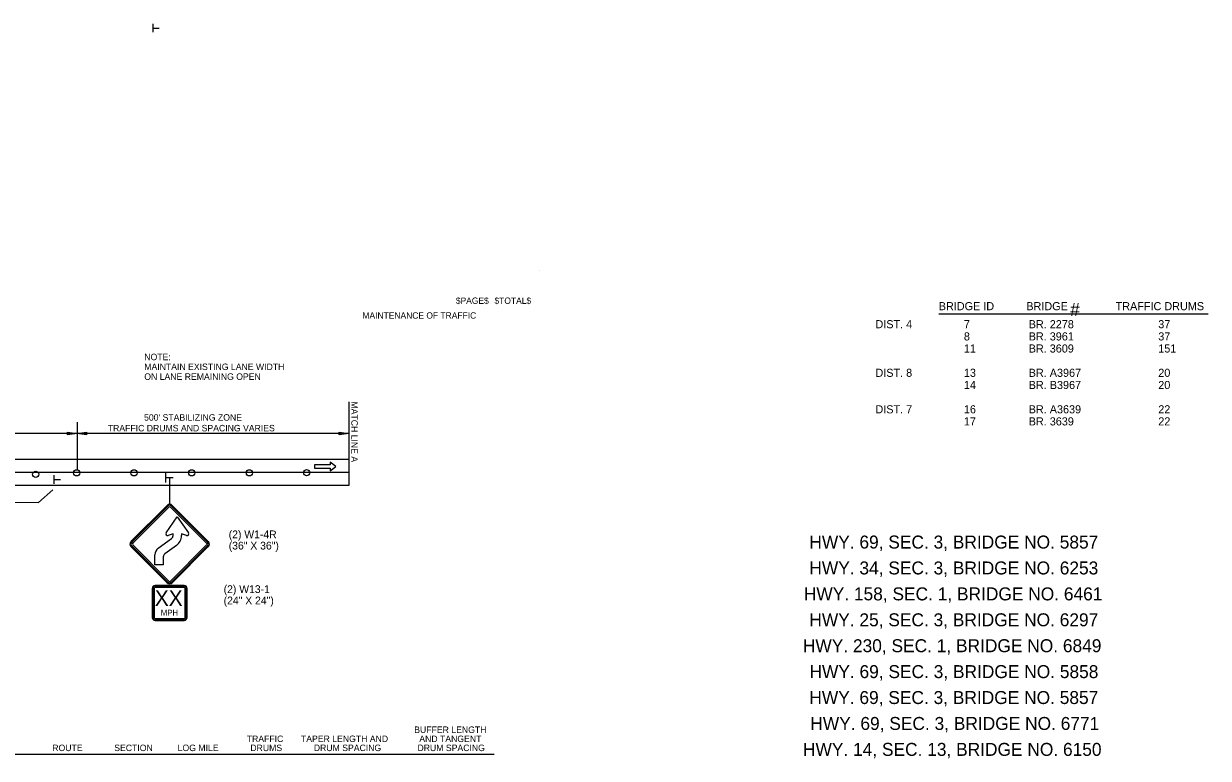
# Model space of a CAD drawing. Extents: x 1930579 to 1937521, y 596183 to 597566.
# Drawn here: x 1936202 to 1937299, y 596886 to 597566 of the extents above; entities that cross this region are included whole.
import ezdxf

# ---------------------------------------------------------------- set-up
doc = ezdxf.new("R2010")
doc.units = 0
for name, color, linetype in [('Default', 7, 'Continuous'), ('P_TC_Signs_Permanent', 7, 'Continuous'), ('R_Annotation', 7, 'Continuous'), ('R_Border', 7, 'Continuous'), ('R_Striping', 7, 'Continuous')]:
    doc.layers.add(name, color=color, linetype=linetype)

msp = doc.modelspace()

# ---------------------------------------------------------------- linework, layer by layer
at = {"layer": 'Default'}
for p, q in [((1936321.9, 597558.1), (1936321.9, 597566)), ((1936322, 597562), (1936327.4, 597562)), ((1936503, 597215.8), (1936503, 597138.5)), ((1936251.3, 597197), (1936251.3, 597152.4)), ((1936251.3, 597186.5), (1935884.1, 597186.5)), ((1936242.4, 597185.2), (1936242.4, 597187.8)), ((1936242.4, 597187.8), (1936251.3, 597186.5)), ((1936251.3, 597186.5), (1936242.4, 597185.2)), ((1936251.3, 597186.5), (1936260.2, 597187.8)), ((1936503, 597186.5), (1936251.3, 597186.5)), ((1936260.2, 597185.2), (1936251.3, 597186.5)), ((1936260.2, 597187.8), (1936260.2, 597185.2)), ((1936494.2, 597185.2), (1936494.2, 597187.8)), ((1936494.2, 597187.8), (1936503, 597186.5)), ((1936503, 597186.5), (1936494.2, 597185.2)), ((1936503, 597162.5), (1935188.5, 597162.5)), ((1936503, 597150.5), (1935188.5, 597150.5)), ((1936230.3, 597139.9), (1936230.3, 597147.9)), ((1936230.4, 597143.8), (1936235.9, 597143.8)), ((1936333.7, 597141), (1936333.7, 597150.6)), ((1936333.9, 597145.8), (1936340.4, 597145.8)), ((1936503, 597138.5), (1935188.5, 597138.5))]:
    msp.add_line(p, q, dxfattribs=at)
for centre in [(1936213.1, 597148.8), (1936251, 597150.1), (1936304.1, 597150.1), (1936357.6, 597150.1), (1936411, 597150.1), (1936463.9, 597150.3)]:
    msp.add_circle(centre, 2.87, dxfattribs=at)
at = {"layer": 'P_TC_Signs_Permanent'}
for p, q in [((1936301.3, 597086.5), (1936334.8, 597119.9)), ((1936302, 597085.9), (1936335.4, 597119.3)), ((1936336.3, 597118.4), (1936302.9, 597084.9)), ((1936371.3, 597084.9), (1936337.9, 597118.4)), ((1936338.9, 597119.3), (1936372.3, 597085.9)), ((1936339.5, 597119.9), (1936372.9, 597086.5)), ((1936326.6, 597080.4), (1936338.9, 597089.3)), ((1936334.8, 597048.3), (1936301.3, 597081.8)), ((1936335.4, 597049), (1936302, 597082.4)), ((1936302.9, 597083.3), (1936336.3, 597049.9)), ((1936343.5, 597082.9), (1936332.6, 597075.1)), ((1936337.9, 597049.9), (1936371.3, 597083.3)), ((1936372.3, 597082.4), (1936338.9, 597049)), ((1936372.9, 597081.8), (1936339.5, 597048.3)), ((1936320.9, 597043.1), (1936320.9, 597016.1)), ((1936321.6, 597043.1), (1936321.6, 597016.1)), ((1936322.7, 597043.1), (1936322.7, 597016.1)), ((1936350.6, 597045.8), (1936323.6, 597045.8)), ((1936350.6, 597045.1), (1936323.6, 597045.1)), ((1936350.6, 597044), (1936323.6, 597044)), ((1936351.5, 597016.1), (1936351.5, 597043.1)), ((1936352.7, 597016.1), (1936352.7, 597043.1)), ((1936353.3, 597016.1), (1936353.3, 597043.1)), ((1936323.6, 597015.2), (1936350.6, 597015.2)), ((1936323.6, 597014.1), (1936350.6, 597014.1)), ((1936323.6, 597013.4), (1936350.6, 597013.4))]:
    msp.add_line(p, q, dxfattribs=at)
for points in [[(1936333.9, 597094.4), (1936344.2, 597109.5), (1936354.5, 597094.4)], [(1936340.3, 597092), (1936340.3, 597093.5), (1936335.7, 597092)], [(1936352.7, 597092), (1936348.2, 597093.5), (1936348.2, 597092)], [(1936331.2, 597072.3), (1936331.2, 597065), (1936323.4, 597065), (1936323.4, 597074.1)]]:
    msp.add_lwpolyline(points, dxfattribs=at)
for centre, radius, start, end in [((1936337.1, 597117.6), 3.38, 45, 135), ((1936337.1, 597117.6), 2.47, 45, 135), ((1936337.1, 597117.6), 1.12, 45, 135), ((1936303.7, 597084.1), 3.37, 135, 225), ((1936303.7, 597084.1), 2.47, 135, 225), ((1936335.2, 597093.5), 1.57, 145.6763, 287.8128), ((1936336.9, 597092), 3.38, 305.7733, 0), ((1936336.9, 597092), 11.2, 305.7733, 0), ((1936353.2, 597093.5), 1.57, 252.1872, 34.3237), ((1936370.6, 597084.1), 2.47, 315, 45), ((1936370.6, 597084.1), 3.37, 315, 45), ((1936303.7, 597084.1), 1.12, 135, 225), ((1936331.2, 597074.1), 7.87, 125.7733, 180), ((1936334.6, 597072.3), 3.38, 125.7733, 180), ((1936370.6, 597084.1), 1.12, 315, 45), ((1936323.6, 597043.1), 2.7, 90, 180), ((1936323.6, 597043.1), 2.03, 90, 180), ((1936323.6, 597043.1), 0.9, 90, 180), ((1936337.1, 597050.7), 3.37, 225, 315), ((1936337.1, 597050.7), 2.47, 225, 315), ((1936337.1, 597050.7), 1.12, 225, 315), ((1936350.6, 597043.1), 2.7, 360, 90), ((1936350.6, 597043.1), 2.03, 360, 90), ((1936350.6, 597043.1), 0.9, 360, 90), ((1936323.6, 597016.1), 2.7, 180, 270), ((1936323.6, 597016.1), 2.03, 180, 270), ((1936323.6, 597016.1), 0.9, 180, 270), ((1936350.6, 597016.1), 2.7, 270, 360), ((1936350.6, 597016.1), 2.03, 270, 360), ((1936350.6, 597016.1), 0.9, 270, 360)]:
    msp.add_arc(centre, radius, start, end, dxfattribs=at)
at = {"layer": 'R_Annotation'}
for p, q in [((1937049.3, 597297.3), (1937298.9, 597297.3)), ((1936337.1, 597145.8), (1936337.1, 597120.9)), ((1936090.3, 596889.7), (1936637.5, 596889.7))]:
    msp.add_line(p, q, dxfattribs=at)
msp.add_lwpolyline([(1936008.1, 597131), (1936019.9, 597124), (1936099.1, 597124), (1936099.8, 597115.7), (1936102.6, 597123.3), (1936215.8, 597122.6), (1936229, 597134.4)], dxfattribs=at)
at = {"layer": 'R_Border'}
msp.add_line((1936679.4, 597337.3), (1936679.4, 597337.3), dxfattribs=at)
at = {"layer": 'R_Striping'}
msp.add_lwpolyline([(1936485.8, 597152), (1936491, 597156), (1936485.8, 597160), (1936485.8, 597157.5), (1936471.1, 597157.5), (1936471.1, 597154.5), (1936485.8, 597154.5)], close=True, dxfattribs=at)

# ---------------------------------------------------------------- texts
at = {"layer": 'Default'}
for s, height, rotation, p in [('MATCH LINE A', 6, 270, (1936505.3, 597216.2)), ("500' STABILIZING ZONE", 6, 360, (1936313.4, 597198.4)), ('TRAFFIC DRUMS AND SPACING VARIES', 6, 360, (1936279.8, 597188.5)), ('HWY. 69, SEC. 3, BRIDGE NO. 5857', 12, 360, (1936929.5, 597080)), ('HWY. 34, SEC. 3, BRIDGE NO. 6253', 12, 360, (1936929.5, 597056)), ('HWY. 158, SEC. 1, BRIDGE NO. 6461', 12, 360, (1936924.4, 597032)), ('HWY. 25, SEC. 3, BRIDGE NO. 6297', 12, 360, (1936929.5, 597008)), ('HWY. 230, SEC. 1, BRIDGE NO. 6849', 12, 360, (1936923.5, 596984)), ('HWY. 69, SEC. 3, BRIDGE NO. 5858', 12, 360, (1936929.6, 596960)), ('HWY. 69, SEC. 3, BRIDGE NO. 5857', 12, 360, (1936929.5, 596936)), ('HWY. 69, SEC. 3, BRIDGE NO. 6771', 12, 360, (1936930.4, 596912)), ('HWY. 14, SEC. 13, BRIDGE NO. 6150', 12, 360, (1936923.6, 596888))]:
    msp.add_text(s, height=height, rotation=rotation, dxfattribs=at).set_placement(p)
at = {"layer": 'P_TC_Signs_Permanent'}
for s, height, p in [('XX', 14.4, (1936323.4, 597026.9)), ('MPH', 5.4, (1936328.9, 597017.9))]:
    msp.add_text(s, height=height, rotation=360, dxfattribs=at).set_placement(p)
at = {"layer": 'R_Annotation'}
for s, height, p in [('BRIDGE ID', 7.5, (1937049.3, 597300.7)), ('BRIDGE ', 7.5, (1937130.4, 597300.7)), ('#', 12, (1937171, 597295.4)), ('TRAFFIC DRUMS', 7.5, (1937213.1, 597300.7)), ('DIST. 4', 7.5, (1936990.7, 597284)), ('7', 7.5, (1937072.6, 597284)), ('BR. 2278', 7.5, (1937132.6, 597284)), ('37', 7.5, (1937252.6, 597284)), ('8', 7.5, (1937072.6, 597272.7)), ('BR. 3961', 7.5, (1937132.6, 597272.7)), ('37', 7.5, (1937252.6, 597272.7)), ('11', 7.5, (1937072.6, 597261.5)), ('BR. 3609', 7.5, (1937132.6, 597261.5)), ('151', 7.5, (1937252.6, 597261.5)), ('NOTE:', 6, (1936313.6, 597254.4)), ('MAINTAIN EXISTING LANE WIDTH', 6, (1936313.6, 597245.3)), ('ON LANE REMAINING OPEN', 6, (1936313.6, 597236.2)), ('DIST. 8', 7.5, (1936990.7, 597239)), ('13', 7.5, (1937072.6, 597239)), ('BR. A3967', 7.5, (1937132.6, 597239)), ('20', 7.5, (1937252.6, 597239)), ('14', 7.5, (1937072.6, 597227.7)), ('BR. B3967', 7.5, (1937132.6, 597227.7)), ('20', 7.5, (1937252.6, 597227.7)), ('DIST. 7', 7.5, (1936990.7, 597205.2)), ('16', 7.5, (1937072.6, 597205.2)), ('BR. A3639', 7.5, (1937132.6, 597205.2)), ('22', 7.5, (1937252.6, 597205.2)), ('17', 7.5, (1937072.6, 597194)), ('BR. 3639', 7.5, (1937132.6, 597194)), ('22', 7.5, (1937252.6, 597194)), ('(2) W1-4R', 7.2, (1936391.8, 597089.5)), ('(36" X 36")', 7.2, (1936391.8, 597079.1)), ('(2) W13-1', 7.2, (1936387.1, 597038.8)), ('(24" X 24")', 7.2, (1936387.1, 597028.3)), ('BUFFER LENGTH', 6, (1936563.6, 596909.2)), ('TRAFFIC', 6, (1936408.5, 596900.8)), ('TAPER LENGTH AND', 6, (1936458.7, 596900.8)), ('AND TANGENT', 6, (1936568.3, 596900.8)), ('ROUTE', 6, (1936228.4, 596892.4)), ('SECTION', 6, (1936285.8, 596892.4)), ('LOG MILE', 6, (1936344.5, 596892.4)), ('DRUMS', 6, (1936411.8, 596892.4)), ('DRUM SPACING', 6, (1936470.6, 596892.4)), ('DRUM SPACING', 6, (1936566.6, 596892.4))]:
    msp.add_text(s, height=height, rotation=360, dxfattribs=at).set_placement(p)
at = {"layer": 'R_Border'}
for s, height, p in [('$PAGE$', 5.86, (1936602.1, 597306.6)), ('$TOTAL$', 5.86, (1936637.9, 597306.6)), ('MAINTENANCE OF TRAFFIC', 5.862, (1936515.6, 597292.9)), ('MAINTENANCE OF TRAFFIC', 5.862, (1936515.6, 597292.9))]:
    msp.add_text(s, height=height, rotation=360, dxfattribs=at).set_placement(p)

doc.saveas('drawing.dxf')
